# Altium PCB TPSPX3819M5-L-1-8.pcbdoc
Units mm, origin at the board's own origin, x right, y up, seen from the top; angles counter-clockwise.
Board outline 16.07 x 16.25 mm, 2 copper layers (Top Layer, Bottom Layer), stack 0 mm thick; 1 components, 0 nets, 5 pads, 0 vias.
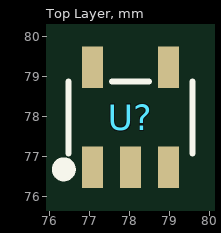
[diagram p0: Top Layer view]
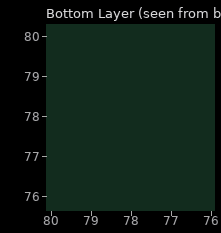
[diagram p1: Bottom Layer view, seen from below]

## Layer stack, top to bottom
Top Layer: signal copper (thickness not stored)
Bottom Layer: signal copper (thickness not stored)

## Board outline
85.92,69.85 69.85,69.85 69.85,86.095 85.92,86.095

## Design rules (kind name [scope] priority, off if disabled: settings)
PasteMaskExpansion "Paste Mask Expansion" [All] p1: expansion=0
SolderMaskExpansion "Solder Mask Expansion" [IsVia] p1: expansion=-25.4 istentingtop=TRUE
SolderMaskExpansion "Solder Mask Expansion" [All] p2: expansion=0.051 istentingtop=FALSE

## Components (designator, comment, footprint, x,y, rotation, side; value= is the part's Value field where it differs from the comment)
U? "TPSPX3819M5-L-1-8" SOT-23-5_L3.0-W1.5-P0.95-LS2.8-BL 78.018,77.973 r0 top

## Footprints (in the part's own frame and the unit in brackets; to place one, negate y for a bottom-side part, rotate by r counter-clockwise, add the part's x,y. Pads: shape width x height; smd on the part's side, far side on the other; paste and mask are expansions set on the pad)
SOT-23-5_L3.0-W1.5-P0.95-LS2.8-BL [mm]
  rect 0.532x1.045 smd: 1(-0.95,-1.25) 2(0,-1.25) 3(0.95,-1.25) 4(0.95,1.25) 5(-0.95,1.25)
  silkscreen extent -1.82,-1.45 1.55,0.9

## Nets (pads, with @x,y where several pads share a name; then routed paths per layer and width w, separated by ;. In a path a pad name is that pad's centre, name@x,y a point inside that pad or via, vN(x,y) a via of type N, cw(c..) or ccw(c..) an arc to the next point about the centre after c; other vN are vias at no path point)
pads on no net: U?.1 U?.2 U?.3 U?.4 U?.5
